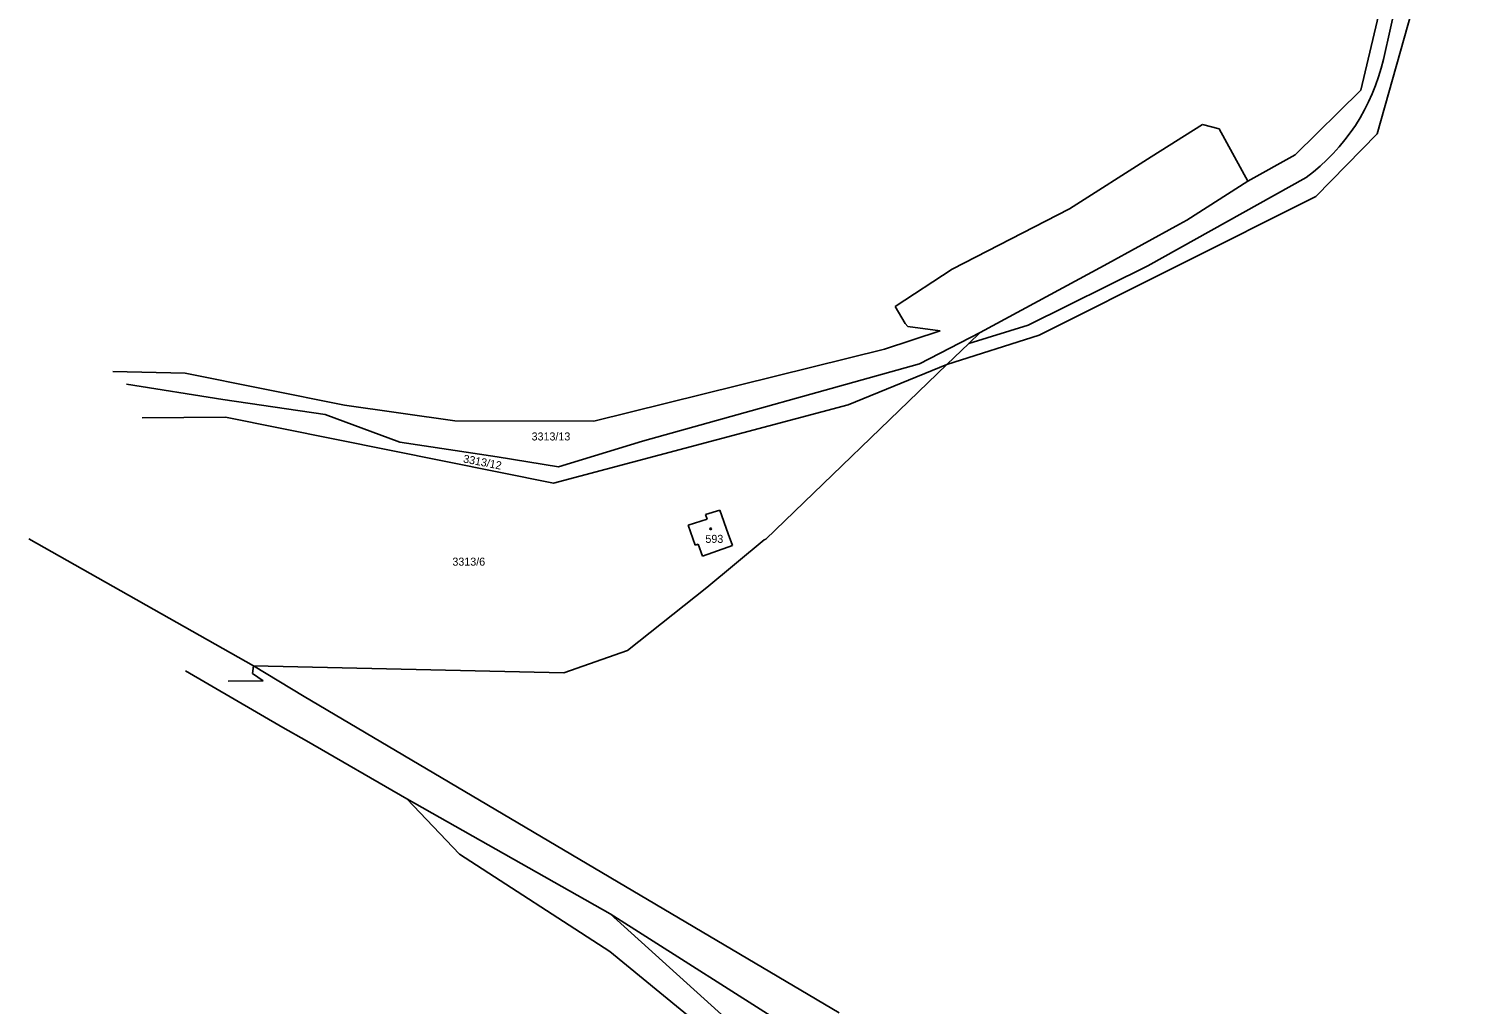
# Model space of a CAD drawing. Extents: x -763205 to -760228, y -1155311 to -1152844.
# Drawn here: x -762649.3 to -762341.6, y -1154249.1 to -1154041.9 of the extents above; entities that cross this region are included whole.
import ezdxf

# ---------------------------------------------------------------- set-up
doc = ezdxf.new("R2010")
doc.units = 0
for name, color, linetype in [('Vrstva 1', 7, 'Continuous'), ('Vrstva 10', 7, 'Continuous'), ('Vrstva 18', 7, 'Continuous'), ('Vrstva 19', 7, 'Continuous'), ('Vrstva 25', 7, 'Continuous'), ('Vrstva 6', 7, 'Continuous')]:
    doc.layers.add(name, color=color, linetype=linetype)

msp = doc.modelspace()

# ---------------------------------------------------------------- linework, layer by layer
at = {"layer": 'Vrstva 1'}
for p, q in [((-762363.03, -1154064.25), (-762341.62, -1153988.29)), ((-762366.48, -1154054.98), (-762362.41, -1154037.61)), ((-762380.43, -1154068.72), (-762366.48, -1154054.98)), ((-762411.06, -1154069.11), (-762400.11, -1154062.22)), ((-762400.11, -1154062.22), (-762396.61, -1154063.14)), ((-762396.61, -1154063.14), (-762390.49, -1154074.27)), ((-762376.08, -1154077.54), (-762363.03, -1154064.25)), ((-762428.35, -1154080.13), (-762411.06, -1154069.11)), ((-762390.49, -1154074.27), (-762380.43, -1154068.72)), ((-762403.47, -1154082.55), (-762390.49, -1154074.27)), ((-762434.8, -1154106.98), (-762376.08, -1154077.54)), ((-762453.3, -1154092.96), (-762428.35, -1154080.13)), ((-762420.99, -1154092.18), (-762404.99, -1154083.39)), ((-762404.99, -1154083.39), (-762403.47, -1154082.55)), ((-762465.4, -1154100.92), (-762453.3, -1154092.96)), ((-762447.32, -1154106.41), (-762420.99, -1154092.18)), ((-762465.4, -1154100.92), (-762463.3, -1154104.5)), ((-762467.68, -1154109.98), (-762455.87, -1154106.08)), ((-762463.3, -1154104.5), (-762462.69, -1154105.15)), ((-762462.69, -1154105.15), (-762455.87, -1154106.08)), ((-762449.73, -1154108.74), (-762447.32, -1154106.41)), ((-762529.41, -1154125.24), (-762467.68, -1154109.98)), ((-762454.4, -1154113.25), (-762434.8, -1154106.98)), ((-762454.4, -1154113.25), (-762449.73, -1154108.74)), ((-762631.56, -1154114.71), (-762616.2, -1154115.1)), ((-762616.2, -1154115.1), (-762582.34, -1154121.88)), ((-762492.84, -1154150.37), (-762454.4, -1154113.25)), ((-762582.34, -1154121.88), (-762558.91, -1154125.21)), ((-762558.91, -1154125.21), (-762529.41, -1154125.24)), ((-762509.36, -1154147.39), (-762505.34, -1154146.12)), ((-762505.66, -1154145.11), (-762502.66, -1154144.16)), ((-762505.66, -1154145.11), (-762505.34, -1154146.12)), ((-762502.66, -1154144.16), (-762500.85, -1154149.21)), ((-762509.36, -1154147.39), (-762507.86, -1154151.59)), ((-762500.85, -1154149.21), (-762499.96, -1154151.72)), ((-762649.34, -1154150.27), (-762601.66, -1154177.29)), ((-762507.86, -1154151.59), (-762507.25, -1154151.38)), ((-762507.25, -1154151.38), (-762506.32, -1154153.99)), ((-762506.32, -1154153.99), (-762500.92, -1154152.06)), ((-762505.4, -1154160.61), (-762493.23, -1154150.46)), ((-762500.92, -1154152.06), (-762499.96, -1154151.72)), ((-762493.23, -1154150.46), (-762492.84, -1154150.37)), ((-762522.25, -1154173.97), (-762505.4, -1154160.61)), ((-762535.77, -1154178.71), (-762522.25, -1154173.97)), ((-762601.84, -1154178.87), (-762601.66, -1154177.29)), ((-762601.66, -1154177.29), (-762535.77, -1154178.71)), ((-762601.66, -1154177.29), (-762590.87, -1154183.76)), ((-762616.1, -1154178.29), (-762595.4, -1154190.36)), ((-762607.03, -1154180.54), (-762599.58, -1154180.46)), ((-762601.84, -1154178.87), (-762599.58, -1154180.46)), ((-762590.87, -1154183.76), (-762477.3, -1154251.01)), ((-762595.4, -1154190.36), (-762590.44, -1154193.22)), ((-762590.44, -1154193.22), (-762569.13, -1154205.52)), ((-762569.13, -1154205.52), (-762525.94, -1154229.95)), ((-762569.13, -1154205.52), (-762557.89, -1154217.25)), ((-762557.89, -1154217.25), (-762526.02, -1154237.96)), ((-762525.94, -1154229.95), (-762471.13, -1154264.73)), ((-762525.94, -1154229.95), (-762513.32, -1154241.33)), ((-762526.02, -1154237.96), (-762486.05, -1154270.63)), ((-762513.32, -1154241.33), (-762486.38, -1154265.63))]:
    msp.add_line(p, q, dxfattribs=at)
at = {"layer": 'Vrstva 10'}
for p, q in [((-762356.66, -1154026.02), (-762361.72, -1154048.42)), ((-762411.71, -1154092.25), (-762378.12, -1154073.48)), ((-762437.13, -1154104.87), (-762411.71, -1154092.25)), ((-762437.13, -1154104.87), (-762449.73, -1154108.74))]:
    msp.add_line(p, q, dxfattribs=at)
msp.add_arc((-762403.533, -1154038.952), 42.872, 306.35419, 347.24198, dxfattribs=at)
at = {"layer": 'Vrstva 25'}
msp.add_circle((-762504.59, -1154148.15), 0.175, dxfattribs=at)
at = {"layer": 'Vrstva 6'}
for p, q in [((-762460.26, -1154113.07), (-762447.32, -1154106.41)), ((-762519.08, -1154129.52), (-762460.26, -1154113.07)), ((-762475.41, -1154121.77), (-762454.4, -1154113.25)), ((-762628.64, -1154117.43), (-762608.2, -1154120.67)), ((-762608.2, -1154120.67), (-762586.46, -1154123.86)), ((-762537.96, -1154138.47), (-762475.41, -1154121.77)), ((-762625.3, -1154124.57), (-762607.64, -1154124.4)), ((-762607.64, -1154124.4), (-762537.96, -1154138.47)), ((-762586.46, -1154123.86), (-762570.62, -1154129.76)), ((-762570.62, -1154129.76), (-762549.94, -1154132.87)), ((-762536.88, -1154134.95), (-762519.08, -1154129.52)), ((-762549.94, -1154132.87), (-762536.88, -1154134.95))]:
    msp.add_line(p, q, dxfattribs=at)

# ---------------------------------------------------------------- texts
at = {"layer": 'Vrstva 18'}
for s, p in [('3313/13', (-762542.603, -1154129.37)), ('3313/6', (-762559.423, -1154155.97))]:
    msp.add_text(s, height=1.7, dxfattribs=at).set_placement(p)
msp.add_text('3313/12', height=1.7, rotation=349.04589, dxfattribs=at).set_placement((-762557.227, -1154134.025))
at = {"layer": 'Vrstva 19'}
msp.add_text('593', height=1.7, dxfattribs=at).set_placement((-762505.693, -1154151.13))

doc.saveas('drawing.dxf')
